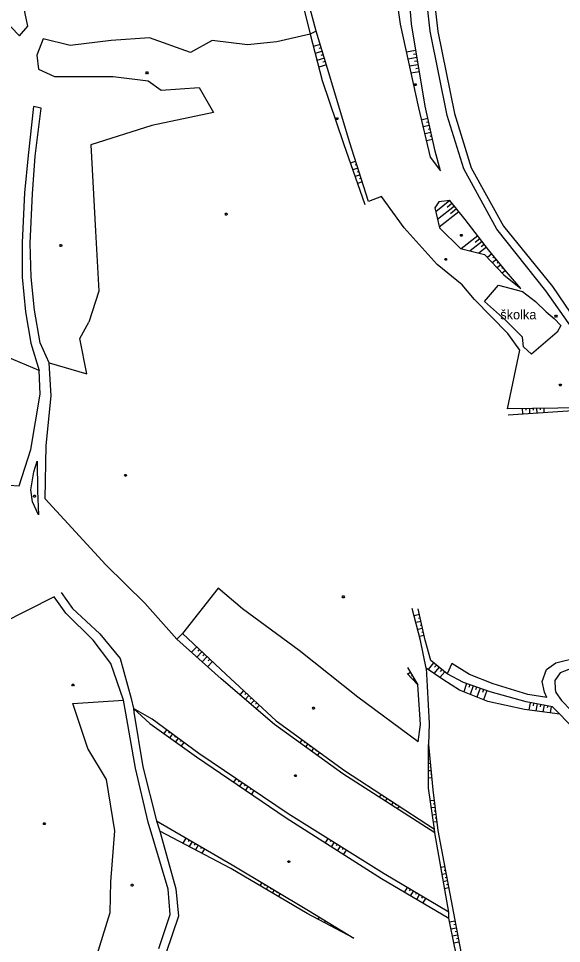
# Model space of a CAD drawing. Extents: x -664960 to -662754, y -993849 to -991145.
# Drawn here: x -663142.5 to -662960.5, y -992369.4 to -992059.4 of the extents above; entities that cross this region are included whole.
import ezdxf

# ---------------------------------------------------------------- set-up
doc = ezdxf.new("R2010")
doc.units = 0
for name, color, linetype in [('Vrstva 12', 7, 'Continuous'), ('Vrstva 13', 7, 'Continuous'), ('Vrstva 27', 7, 'Continuous'), ('Vrstva 28', 7, 'Continuous'), ('Vrstva 37', 7, 'Continuous'), ('Vrstva 63', 7, 'Continuous'), ('Vrstva 8', 7, 'Continuous')]:
    doc.layers.add(name, color=color, linetype=linetype)

msp = doc.modelspace()

# ---------------------------------------------------------------- linework, layer by layer
at = {"layer": 'Vrstva 12'}
msp.add_lwpolyline([(-662986.33, -992154.24), (-662981.63, -992148.77), (-662973.54, -992150.81), (-662969.23, -992154.22), (-662965.6, -992157.65), (-662962.93, -992159.87), (-662960.74, -992162.31), (-662961.96, -992164.49), (-662970.59, -992171.84), (-662973.27, -992169.44), (-662973.53, -992166.19), (-662979.21, -992160.46), (-662986.33, -992154.24)], dxfattribs=at)
at = {"layer": 'Vrstva 13'}
for points in [[(-663099.223, -992077.273), (-663099.043, -992077.573), (-663099.223, -992077.873), (-663099.583, -992077.873), (-663099.763, -992077.573), (-663099.583, -992077.273), (-663099.223, -992077.273)], [(-663035.561, -992092.645), (-663035.381, -992092.945), (-663035.561, -992093.245), (-663035.921, -992093.245), (-663036.101, -992092.945), (-663035.921, -992092.645), (-663035.561, -992092.645)], [(-663072.668, -992124.658), (-663072.488, -992124.958), (-663072.668, -992125.258), (-663073.028, -992125.258), (-663073.208, -992124.958), (-663073.028, -992124.658), (-663072.668, -992124.658)], [(-662993.894, -992131.746), (-662993.714, -992132.046), (-662993.894, -992132.346), (-662994.254, -992132.346), (-662994.434, -992132.046), (-662994.254, -992131.746), (-662993.894, -992131.746)], [(-663128.081, -992135.141), (-663127.901, -992135.441), (-663128.081, -992135.741), (-663128.441, -992135.741), (-663128.621, -992135.441), (-663128.441, -992135.141), (-663128.081, -992135.141)], [(-662999.092, -992139.763), (-662998.912, -992140.063), (-662999.092, -992140.363), (-662999.452, -992140.363), (-662999.632, -992140.063), (-662999.452, -992139.763), (-662999.092, -992139.763)], [(-662960.705, -992181.911), (-662960.525, -992182.211), (-662960.705, -992182.511), (-662961.065, -992182.511), (-662961.245, -992182.211), (-662961.065, -992181.911), (-662960.705, -992181.911)], [(-663106.411, -992212.177), (-663106.231, -992212.477), (-663106.411, -992212.777), (-663106.771, -992212.777), (-663106.951, -992212.477), (-663106.771, -992212.177), (-663106.411, -992212.177)], [(-663136.92, -992219.178), (-663136.74, -992219.478), (-663136.92, -992219.778), (-663137.28, -992219.778), (-663137.46, -992219.478), (-663137.28, -992219.178), (-663136.92, -992219.178)], [(-663033.448, -992252.879), (-663033.268, -992253.179), (-663033.448, -992253.479), (-663033.808, -992253.479), (-663033.988, -992253.179), (-663033.808, -992252.879), (-663033.448, -992252.879)], [(-663043.398, -992290.19), (-663043.218, -992290.49), (-663043.398, -992290.79), (-663043.758, -992290.79), (-663043.938, -992290.49), (-663043.758, -992290.19), (-663043.398, -992290.19)], [(-663049.478, -992312.803), (-663049.298, -992313.103), (-663049.478, -992313.403), (-663049.838, -992313.403), (-663050.018, -992313.103), (-663049.838, -992312.803), (-663049.478, -992312.803)], [(-663133.634, -992328.914), (-663133.454, -992329.214), (-663133.634, -992329.514), (-663133.994, -992329.514), (-663134.174, -992329.214), (-663133.994, -992328.914), (-663133.634, -992328.914)], [(-663051.689, -992341.634), (-663051.509, -992341.934), (-663051.689, -992342.234), (-663052.049, -992342.234), (-663052.229, -992341.934), (-663052.049, -992341.634), (-663051.689, -992341.634)], [(-663104.2, -992349.548), (-663104.02, -992349.848), (-663104.2, -992350.148), (-663104.56, -992350.148), (-663104.74, -992349.848), (-663104.56, -992349.548), (-663104.2, -992349.548)]]:
    msp.add_lwpolyline(points, dxfattribs=at)
at = {"layer": 'Vrstva 27'}
for points in [[(-662956.94, -992163.1), (-662965.75, -992150.64), (-662982.18, -992130.02), (-662993.22, -992109.76), (-662998.77, -992091.85), (-663004.49, -992063.62), (-663006.99, -992041.22)], [(-663004.54, -992041.19), (-663001.94, -992063.69), (-662996.31, -992091.2), (-662990.73, -992109.37), (-662979.93, -992128.92), (-662963.51, -992149.14), (-662955.49, -992161.05)], [(-663133.52, -992220.36), (-663133.15, -992202.51), (-663131.56, -992185.84), (-663132.13, -992174.75), (-663135.23, -992168.06), (-663137.07, -992157.15), (-663138.22, -992146.01), (-663138.54, -992134.69), (-663137.81, -992118.08), (-663136.87, -992105.51), (-663134.82, -992089.45), (-663137.47, -992088.88), (-663139.17, -992105.28), (-663140.5, -992117.84), (-663141.25, -992134.43), (-663141.2, -992146.02), (-663140.1, -992157.7), (-663138.31, -992168.2), (-663135.5, -992177.39)], [(-663142.21, -992216.02), (-663138.35, -992203.78), (-663135.15, -992185.22), (-663135.5, -992177.39)], [(-663138.34, -992217.33), (-663137.37, -992211.34), (-663136.18, -992207.74), (-663136.08, -992217.71)], [(-663095.49, -992371.02), (-663091.69, -992359.65), (-663092.35, -992351.14), (-663098.96, -992328.72), (-663103.21, -992310.62), (-663106.52, -992292.18), (-663107.31, -992287.87), (-663111.51, -992275.52), (-663117.42, -992267.67), (-663126.55, -992258.71), (-663130.51, -992253.17)], [(-663128.11, -992251.69), (-663124.33, -992257.14), (-663115.22, -992265.59), (-663108.37, -992273.86), (-663104.66, -992287.27), (-663103.97, -992290.57), (-663103.77, -992291.85), (-663100.82, -992310.22), (-663096.2, -992328.31), (-663095.1, -992331.72)], [(-662965.43, -992286.95), (-662966.22, -992285.16), (-662966.99, -992281.54), (-662965.49, -992277.55), (-662962.4, -992275.33), (-662954.24, -992273.28)], [(-663005.87, -992277.15), (-663005.49, -992283.11), (-663004.79, -992295.66), (-663005.05, -992302.63)], [(-662965.43, -992286.95), (-662971.76, -992285.89), (-662983.35, -992282.36), (-662991.29, -992279.28), (-662997.21, -992275.57), (-662998.86, -992278.96)], [(-662958.04, -992277.5), (-662960.9, -992278.71), (-662962.71, -992281.29), (-662962.62, -992284.25), (-662962.44, -992285.29)], [(-663008.55, -992301.75), (-663007.8, -992296), (-663008.63, -992282.68)], [(-662962.44, -992285.29), (-662960.53, -992287.98), (-662957.278, -992291.341), (-662954.15, -992294.72), (-662938.36, -992310.24), (-662929.08, -992320.03), (-662920.86, -992330.7), (-662912.84, -992351.32), (-662905.9, -992372.83), (-662896.75, -992402.99), (-662892.28, -992419.6), (-662886.17, -992439.46), (-662883.07, -992447.93), (-662879.65, -992454.82), (-662876.1, -992460.53), (-662867.14, -992470.96), (-662855.91, -992480.61), (-662847.69, -992487.2), (-662824.02, -992504.16), (-662808.83, -992512.81)], [(-662963.5, -992290.01), (-662961.05, -992292.51), (-662956.54, -992297.17), (-662941.08, -992312.11), (-662931.7, -992322.28), (-662923.87, -992332.38), (-662915.46, -992352.13), (-662908.55, -992373.66)], [(-663095.1, -992331.72), (-663089.72, -992351.06), (-663088.9, -992360.19), (-663092.97, -992372.36)]]:
    msp.add_lwpolyline(points, dxfattribs=at)
at = {"layer": 'Vrstva 28'}
msp.add_lwpolyline([(-663124.04, -992282.43), (-663123.86, -992282.73), (-663124.04, -992283.03), (-663124.4, -992283.03), (-663124.58, -992282.73), (-663124.4, -992282.43), (-663124.04, -992282.43)], dxfattribs=at)
at = {"layer": 'Vrstva 37'}
msp.add_lwpolyline([(-663009.28, -992081.26), (-663009.1, -992081.56), (-663009.28, -992081.86), (-663009.64, -992081.86), (-663009.82, -992081.56), (-663009.64, -992081.26), (-663009.28, -992081.26)], dxfattribs=at)
at = {"layer": 'Vrstva 63'}
for p, q in [((-663041.334, -992068.037), (-663043.672, -992068.745)), ((-663040.639, -992070.334), (-663043.065, -992071.069)), ((-663040.986, -992069.186), (-663041.78, -992069.426)), ((-663009.268, -992070.116), (-663012.524, -992070.645)), ((-663039.943, -992072.631), (-663042.458, -992073.393)), ((-663040.291, -992071.483), (-663041.113, -992071.732)), ((-663008.882, -992072.485), (-663012.012, -992072.994)), ((-663009.075, -992071.3), (-663010.138, -992071.473)), ((-663039.247, -992074.928), (-663041.851, -992075.717)), ((-663039.595, -992073.78), (-663040.447, -992074.038)), ((-663008.497, -992074.854), (-663011.5, -992075.342)), ((-663008.69, -992073.669), (-663009.711, -992073.835)), ((-663008.305, -992076.038), (-663009.283, -992076.197)), ((-663008.112, -992077.223), (-663010.988, -992077.69)), ((-663005.294, -992092.891), (-663007.471, -992093.389)), ((-663004.759, -992095.231), (-663006.909, -992095.722)), ((-663005.026, -992094.061), (-663005.747, -992094.226)), ((-663004.224, -992097.57), (-663006.347, -992098.056)), ((-663004.491, -992096.4), (-663005.203, -992096.563)), ((-663003.688, -992099.91), (-663005.785, -992100.389)), ((-663003.956, -992098.74), (-663004.659, -992098.901)), ((-663029.426, -992107.231), (-663031.259, -992107.809)), ((-663028.705, -992109.52), (-663030.473, -992110.077)), ((-663029.066, -992108.376), (-663029.665, -992108.565)), ((-663028.345, -992110.665), (-663028.922, -992110.847)), ((-663027.984, -992111.81), (-663029.686, -992112.346)), ((-663027.624, -992112.954), (-663028.18, -992113.129)), ((-663027.263, -992114.099), (-663028.9, -992114.614)), ((-662997.88, -992120.36), (-663002.631, -992124.147)), ((-662996.384, -992122.237), (-663002.049, -992126.753)), ((-662997.132, -992121.298), (-662998.866, -992122.681)), ((-662995.636, -992123.175), (-662997.675, -992124.8)), ((-662994.888, -992124.113), (-663001.468, -992129.359)), ((-662988.566, -992132.213), (-662994.135, -992136.515)), ((-662987.098, -992134.113), (-662991.159, -992137.249)), ((-662987.832, -992133.163), (-662989.436, -992134.401)), ((-662986.365, -992135.062), (-662987.466, -992135.913)), ((-662985.631, -992136.012), (-662988.183, -992137.983)), ((-662983.851, -992138.235), (-662985.33, -992139.448)), ((-662982.329, -992140.09), (-662983.69, -992141.208)), ((-662983.09, -992139.163), (-662983.563, -992139.551)), ((-662981.568, -992141.018), (-662982.002, -992141.374)), ((-662980.806, -992141.946), (-662982.051, -992142.967)), ((-662980.045, -992142.873), (-662980.44, -992143.197)), ((-662979.284, -992143.801), (-662980.412, -992144.727)), ((-662940.46, -992189.74), (-662978.64, -992190.16)), ((-662978.36, -992192.16), (-662940.46, -992189.74)), ((-662973.627, -992190.105), (-662973.608, -992191.857)), ((-662972.427, -992190.092), (-662972.421, -992190.654)), ((-662971.227, -992190.078), (-662971.209, -992191.703)), ((-662970.027, -992190.065), (-662970.022, -992190.585)), ((-662968.827, -992190.052), (-662968.811, -992191.55)), ((-662967.627, -992190.039), (-662967.622, -992190.517)), ((-662966.428, -992190.026), (-662966.412, -992191.397)), ((-663008.063, -992259.132), (-663009.899, -992259.53)), ((-663007.555, -992261.477), (-663009.289, -992261.853)), ((-663007.809, -992260.305), (-663008.403, -992260.433)), ((-663007.3, -992262.65), (-663007.861, -992262.772)), ((-663007.046, -992263.823), (-663008.679, -992264.177)), ((-663006.792, -992264.995), (-663007.319, -992265.11)), ((-663006.537, -992266.168), (-663008.069, -992266.5)), ((-663082.72, -992269.949), (-663084.455, -992271.793)), ((-663080.972, -992271.594), (-663082.672, -992273.401)), ((-663081.846, -992270.772), (-663082.418, -992271.379)), ((-663079.224, -992273.238), (-663080.89, -992275.009)), ((-663080.098, -992272.416), (-663080.659, -992273.012)), ((-663077.476, -992274.883), (-663079.107, -992276.616)), ((-663078.35, -992274.06), (-663078.899, -992274.644)), ((-663012.15, -992276.85), (-663008.63, -992282.68)), ((-663003.368, -992275.289), (-663005.232, -992277.577)), ((-663001.507, -992276.804), (-663003.228, -992278.918)), ((-663002.437, -992276.046), (-663003.034, -992276.779)), ((-663000.576, -992277.562), (-663001.126, -992278.237)), ((-663012.22, -992278.87), (-663008.63, -992282.68)), ((-663011.111, -992278.571), (-663011.997, -992279.106)), ((-663010.491, -992279.598), (-663010.712, -992279.732)), ((-663009.87, -992280.625), (-663010.314, -992280.893)), ((-662999.646, -992278.32), (-663001.225, -992280.258)), ((-663009.25, -992281.653), (-663009.324, -992281.697)), ((-663008.63, -992282.68), (-663008.63, -992282.68)), ((-662992.331, -992282.253), (-662993.283, -992284.999)), ((-662991.197, -992282.647), (-662991.521, -992283.581)), ((-662990.063, -992283.04), (-662991.057, -992285.904)), ((-662988.93, -992283.433), (-662989.267, -992284.407)), ((-662987.796, -992283.826), (-662988.831, -992286.81)), ((-662986.662, -992284.219), (-662987.013, -992285.233)), ((-663067.021, -992284.641), (-663068.319, -992286.041)), ((-663066.141, -992285.457), (-663066.562, -992285.911)), ((-663065.261, -992286.273), (-663066.492, -992287.6)), ((-663064.382, -992287.09), (-663064.78, -992287.519)), ((-662985.528, -992284.612), (-662986.605, -992287.716)), ((-663063.502, -992287.906), (-663064.665, -992289.159)), ((-663062.622, -992288.722), (-663062.998, -992289.127)), ((-663061.742, -992289.538), (-663062.838, -992290.719)), ((-662971.034, -992288.67), (-662971.466, -992291.099)), ((-662969.852, -992288.88), (-662969.993, -992289.672)), ((-662968.671, -992289.09), (-662969.085, -992291.421)), ((-662967.489, -992289.3), (-662967.624, -992290.06)), ((-662966.308, -992289.51), (-662966.705, -992291.744)), ((-662965.126, -992289.721), (-662965.256, -992290.448)), ((-662963.945, -992289.931), (-662964.325, -992292.066)), ((-663092.85, -992297.73), (-663093.743, -992298.955)), ((-663091.881, -992298.437), (-663092.176, -992298.843)), ((-663090.911, -992299.144), (-663091.794, -992300.356)), ((-663089.941, -992299.851), (-663090.234, -992300.253)), ((-663088.972, -992300.559), (-663089.846, -992301.757)), ((-663088.002, -992301.266), (-663088.292, -992301.662)), ((-663087.033, -992301.973), (-663087.897, -992303.158)), ((-663047.455, -992301.052), (-663048.219, -992302.104)), ((-663046.484, -992301.756), (-663046.738, -992302.107)), ((-663045.512, -992302.461), (-663046.275, -992303.512)), ((-663044.541, -992303.166), (-663044.795, -992303.516)), ((-663043.57, -992303.871), (-663044.331, -992304.92)), ((-663042.599, -992304.575), (-663042.852, -992304.925)), ((-663041.627, -992305.28), (-663042.388, -992306.328)), ((-663004.682, -992306.683), (-663005.042, -992306.716)), ((-663004.464, -992309.074), (-663005.037, -992309.126)), ((-663004.573, -992307.878), (-663004.728, -992307.893)), ((-663004.247, -992311.464), (-663005.032, -992311.535)), ((-663004.356, -992310.269), (-663004.582, -992310.289)), ((-663069.534, -992314.082), (-663070.359, -992315.301)), ((-663068.54, -992314.754), (-663068.816, -992315.161)), ((-663004.03, -992313.854), (-663005.027, -992313.945)), ((-663004.138, -992312.659), (-663004.435, -992312.686)), ((-663067.546, -992315.427), (-663068.376, -992316.653)), ((-663066.553, -992316.1), (-663066.83, -992316.509)), ((-663065.559, -992316.772), (-663066.393, -992318.004)), ((-663064.565, -992317.445), (-663064.844, -992317.856)), ((-663063.571, -992318.118), (-663064.41, -992319.356)), ((-663020.945, -992319.402), (-663021.589, -992320.388)), ((-663019.941, -992320.059), (-663020.153, -992320.384)), ((-663018.936, -992320.715), (-663019.57, -992321.685)), ((-663017.931, -992321.371), (-663018.141, -992321.691)), ((-663003.227, -992321.412), (-663004.429, -992321.562)), ((-663016.927, -992322.028), (-663017.55, -992322.981)), ((-663015.922, -992322.684), (-663016.128, -992322.999)), ((-663014.918, -992323.34), (-663015.53, -992324.278)), ((-663002.931, -992323.794), (-663004.097, -992323.939)), ((-663003.079, -992322.603), (-663003.473, -992322.652)), ((-663002.636, -992326.176), (-663003.764, -992326.316)), ((-663002.783, -992324.985), (-663003.165, -992325.032)), ((-663002.488, -992327.367), (-663002.857, -992327.413)), ((-663002.34, -992328.558), (-663003.431, -992328.693)), ((-663086.356, -992334.037), (-663087.378, -992335.795)), ((-663085.318, -992334.64), (-663085.651, -992335.212)), ((-663084.281, -992335.244), (-663085.254, -992336.916)), ((-663083.244, -992335.847), (-663083.56, -992336.39)), ((-663082.207, -992336.451), (-663083.13, -992338.037)), ((-663081.169, -992337.054), (-663081.468, -992337.568)), ((-663038.788, -992334.236), (-663039.65, -992335.61)), ((-663037.772, -992334.874), (-663038.06, -992335.333)), ((-663036.755, -992335.512), (-663037.623, -992336.895)), ((-663035.739, -992336.15), (-663036.029, -992336.612)), ((-663034.722, -992336.787), (-663035.596, -992338.18)), ((-663080.132, -992337.658), (-663081.005, -992339.159)), ((-663033.706, -992337.425), (-663033.998, -992337.89)), ((-663032.689, -992338.063), (-663033.569, -992339.466)), ((-662999.662, -992343.694), (-663000.946, -992343.938)), ((-662999.214, -992346.052), (-663000.529, -992346.302)), ((-662999.438, -992344.873), (-662999.871, -992344.955)), ((-663060.939, -992348.967), (-663061.565, -992350.017)), ((-662998.767, -992348.41), (-663000.111, -992348.665)), ((-662998.991, -992347.231), (-662999.433, -992347.315)), ((-663059.908, -992349.582), (-663060.116, -992349.93)), ((-663058.878, -992350.196), (-663059.497, -992351.235)), ((-663057.847, -992350.811), (-663058.052, -992351.155)), ((-663056.816, -992351.425), (-663057.429, -992352.454)), ((-663055.785, -992352.04), (-663055.988, -992352.381)), ((-663012.269, -992350.616), (-663013.151, -992352.102)), ((-663011.237, -992351.229), (-663011.531, -992351.724)), ((-663010.205, -992351.842), (-663011.087, -992353.326)), ((-663009.173, -992352.454), (-663009.467, -992352.949)), ((-662998.319, -992350.768), (-662999.693, -992351.029)), ((-662998.543, -992349.589), (-662998.995, -992349.675)), ((-663054.755, -992352.655), (-663055.361, -992353.672)), ((-663008.142, -992353.067), (-663009.023, -992354.551)), ((-663007.11, -992353.68), (-663007.403, -992354.174)), ((-663006.078, -992354.292), (-663006.959, -992355.775)), ((-663041.653, -992360.521), (-663042.103, -992361.257)), ((-663040.629, -992361.146), (-663040.766, -992361.37)), ((-663039.605, -992361.772), (-663039.976, -992362.378)), ((-662996.213, -992361.857), (-662998.005, -992362.198)), ((-663038.581, -992362.398), (-663038.691, -992362.578)), ((-663037.557, -992363.023), (-663037.848, -992363.5)), ((-663036.533, -992363.649), (-663036.617, -992363.786)), ((-663035.509, -992364.275), (-663035.721, -992364.621)), ((-662995.766, -992364.215), (-662997.515, -992364.548)), ((-662995.989, -992363.036), (-662996.579, -992363.148)), ((-662995.318, -992366.573), (-662997.024, -992366.897)), ((-662995.542, -992365.394), (-662996.117, -992365.504)), ((-662995.094, -992367.752), (-662995.655, -992367.859)), ((-662994.87, -992368.931), (-662996.534, -992369.247))]:
    msp.add_line(p, q, dxfattribs=at)
for points in [[(-663025.19, -992120.68), (-663031.49, -992100.68), (-663038.12, -992078.65), (-663042.66, -992063.66), (-663045.25, -992053.96), (-663050.7, -992036.29), (-663059.98, -992002.07), (-663061.95, -991991.23), (-663070.35, -991968.82), (-663080.1, -991937.19), (-663084.39, -991922.42), (-663089.95, -991918.77)], [(-663089.95, -991918.77), (-663085.41, -991924.52), (-663076.03, -991955.45), (-663070.69, -991975.57), (-663064.35, -991992.78), (-663061.86, -992001.51), (-663053.66, -992036.42), (-663046.87, -992055.99), (-663044.75, -992064.62), (-663040.7, -992080.12), (-663033.54, -992101.23), (-663026.45, -992121.68)], [(-663135.5, -992177.39), (-663146.12, -992172.92), (-663148.32, -992161.18), (-663153.95, -992156.98), (-663151.59, -992136.77), (-663152.6, -992124.17), (-663150.97, -992116.21), (-663155.04, -992089.45), (-663158.13, -992080.36), (-663159.72, -992069.81), (-663162.02, -992063.04), (-663161.85, -992055.48), (-663155.08, -992056), (-663149.1, -992058.44), (-663145.07, -992062.16), (-663142.16, -992065.15), (-663139.33, -992061.92), (-663142.33, -992047.53), (-663144.85, -992030.82), (-663145.27, -992022.76), (-663142.06, -992015.64), (-663138.15, -992009.85), (-663115.65, -992002.94)], [(-663015.08, -992006.1), (-663020.1, -992010.46), (-663022.79, -992016.08), (-663022.6, -992023.57), (-663019.76, -992029.97), (-663016.47, -992047.75), (-663014.58, -992061.22), (-663008.46, -992089.28), (-663004.47, -992105.85), (-663001.1, -992110.39), (-663002.78, -992103.88), (-663006.23, -992088.8), (-663010.73, -992061.12), (-663012.18, -992043.13), (-663014.48, -992027.29), (-663015.08, -992006.1)], [(-663042.66, -992063.66), (-663044.75, -992064.62), (-663055.85, -992067.21), (-663065.68, -992068.18), (-663077.61, -992066.69), (-663084.86, -992070.72), (-663098.59, -992065.86), (-663111.39, -992066.78), (-663125.19, -992068.41), (-663134.2, -992066.19), (-663136.34, -992071.67), (-663135.74, -992076.4), (-663130.35, -992078.76), (-663110.71, -992078.76), (-663099.03, -992080.27), (-663094.66, -992083.35), (-663081.97, -992082.52), (-663077.12, -992090.87), (-663097.75, -992095.21), (-663118.27, -992101.75), (-663116.66, -992130.65), (-663115.52, -992150.8), (-663118.91, -992161.17)], [(-662978.64, -992190.16), (-662974.44, -992170.52), (-662978.53, -992164.92), (-662989.67, -992153.51), (-662993.76, -992148.65), (-663002.13, -992141.86), (-663013.2, -992129.5), (-663020.81, -992118.99), (-663025.19, -992120.68)], [(-662974.13, -992149.88), (-662978.94, -992144.22), (-662984.93, -992136.92), (-662992.77, -992126.77), (-662997.88, -992120.36), (-663001.65, -992120.79), (-663002.92, -992122.85), (-663001.43, -992129.53), (-662994.4, -992136.45), (-662986.25, -992138.46), (-662979.85, -992145.33), (-662974.13, -992149.88)], [(-663132.13, -992174.75), (-663119.54, -992178.48), (-663121.94, -992166.61), (-663118.91, -992161.17)], [(-663130.51, -992253.17), (-663148.34, -992262.24), (-663157.52, -992257.9), (-663157.92, -992252.84), (-663162.34, -992230.18), (-663163.09, -992214.61), (-663142.21, -992216.02)], [(-663136.08, -992217.71), (-663135.77, -992225.7), (-663137.73, -992221.35), (-663138.34, -992217.33)], [(-663008.55, -992301.75), (-663028.8, -992286.87), (-663048.36, -992271.17), (-663067.43, -992257.21), (-663075.55, -992250.29), (-663087.45, -992265.5), (-663089.36, -992267.37), (-663100.16, -992255.34), (-663113.22, -992242.49), (-663133.52, -992220.36)], [(-662961.05, -992292.51), (-662972.86, -992290.91), (-662985.17, -992288.3), (-662994.68, -992284.43), (-663000.31, -992280.87), (-663005.87, -992277.15), (-663007.71, -992267.87), (-663010.55, -992257.05)], [(-662963.5, -992290.01), (-662972.38, -992288.43), (-662984.41, -992285), (-662993.35, -992281.9), (-662998.86, -992278.96), (-663004.25, -992274.57), (-663006.19, -992267.77), (-663008.48, -992257.21)], [(-663087.45, -992265.5), (-663072.94, -992279.15), (-663056.07, -992294.8), (-663033.18, -992311.41), (-663003.1, -992331.06)], [(-663003, -992332.32), (-663033.77, -992312.57), (-663056.66, -992295.99), (-663074.59, -992280.69), (-663089.36, -992267.37)], [(-663119.1, -992427.6), (-663119.91, -992403.54), (-663119.07, -992382.76), (-663111.72, -992359.02), (-663111.56, -992348.76), (-663110.23, -992331.66), (-663112.94, -992314.42), (-663119.22, -992303.97), (-663124.27, -992288.96), (-663107.31, -992287.87)], [(-663103.97, -992290.57), (-663098.41, -992295.6), (-663082.83, -992306.8), (-663052.8, -992327.27), (-663020.79, -992347.57), (-662998.27, -992360.93)], [(-662998.3, -992358.91), (-663019.91, -992346.08), (-663052.06, -992325.91), (-663081.99, -992305.65), (-663097.65, -992294.23), (-663103.97, -992290.57)], [(-663005.05, -992302.63), (-663003.66, -992317.92), (-663001.97, -992331.54), (-662994.69, -992369.88), (-662992.61, -992380.79)], [(-662991.84, -992387.34), (-662993.89, -992380.32), (-662996.31, -992370.32), (-662998.27, -992360.93), (-662998.3, -992358.91), (-663003, -992332.32), (-663003.1, -992331.06), (-663005.02, -992317.34), (-663005.05, -992302.63)], [(-663096.2, -992328.31), (-663070.88, -992343.04), (-663045.32, -992358.28), (-663030.05, -992367.61), (-663045.74, -992359.34), (-663071.32, -992344.27), (-663095.1, -992331.72)]]:
    msp.add_lwpolyline(points, dxfattribs=at)
at = {"layer": 'Vrstva 8'}
msp.add_lwpolyline([(-662962.18, -992158.82), (-662962, -992159.12), (-662962.18, -992159.42), (-662962.54, -992159.42), (-662962.72, -992159.12), (-662962.54, -992158.82), (-662962.18, -992158.82)], dxfattribs=at)

# ---------------------------------------------------------------- texts
at = {"layer": 'Vrstva 63'}
msp.add_text('školka', height=3.2, dxfattribs=at).set_placement((-662981.022, -992160.193))

doc.saveas('drawing.dxf')
